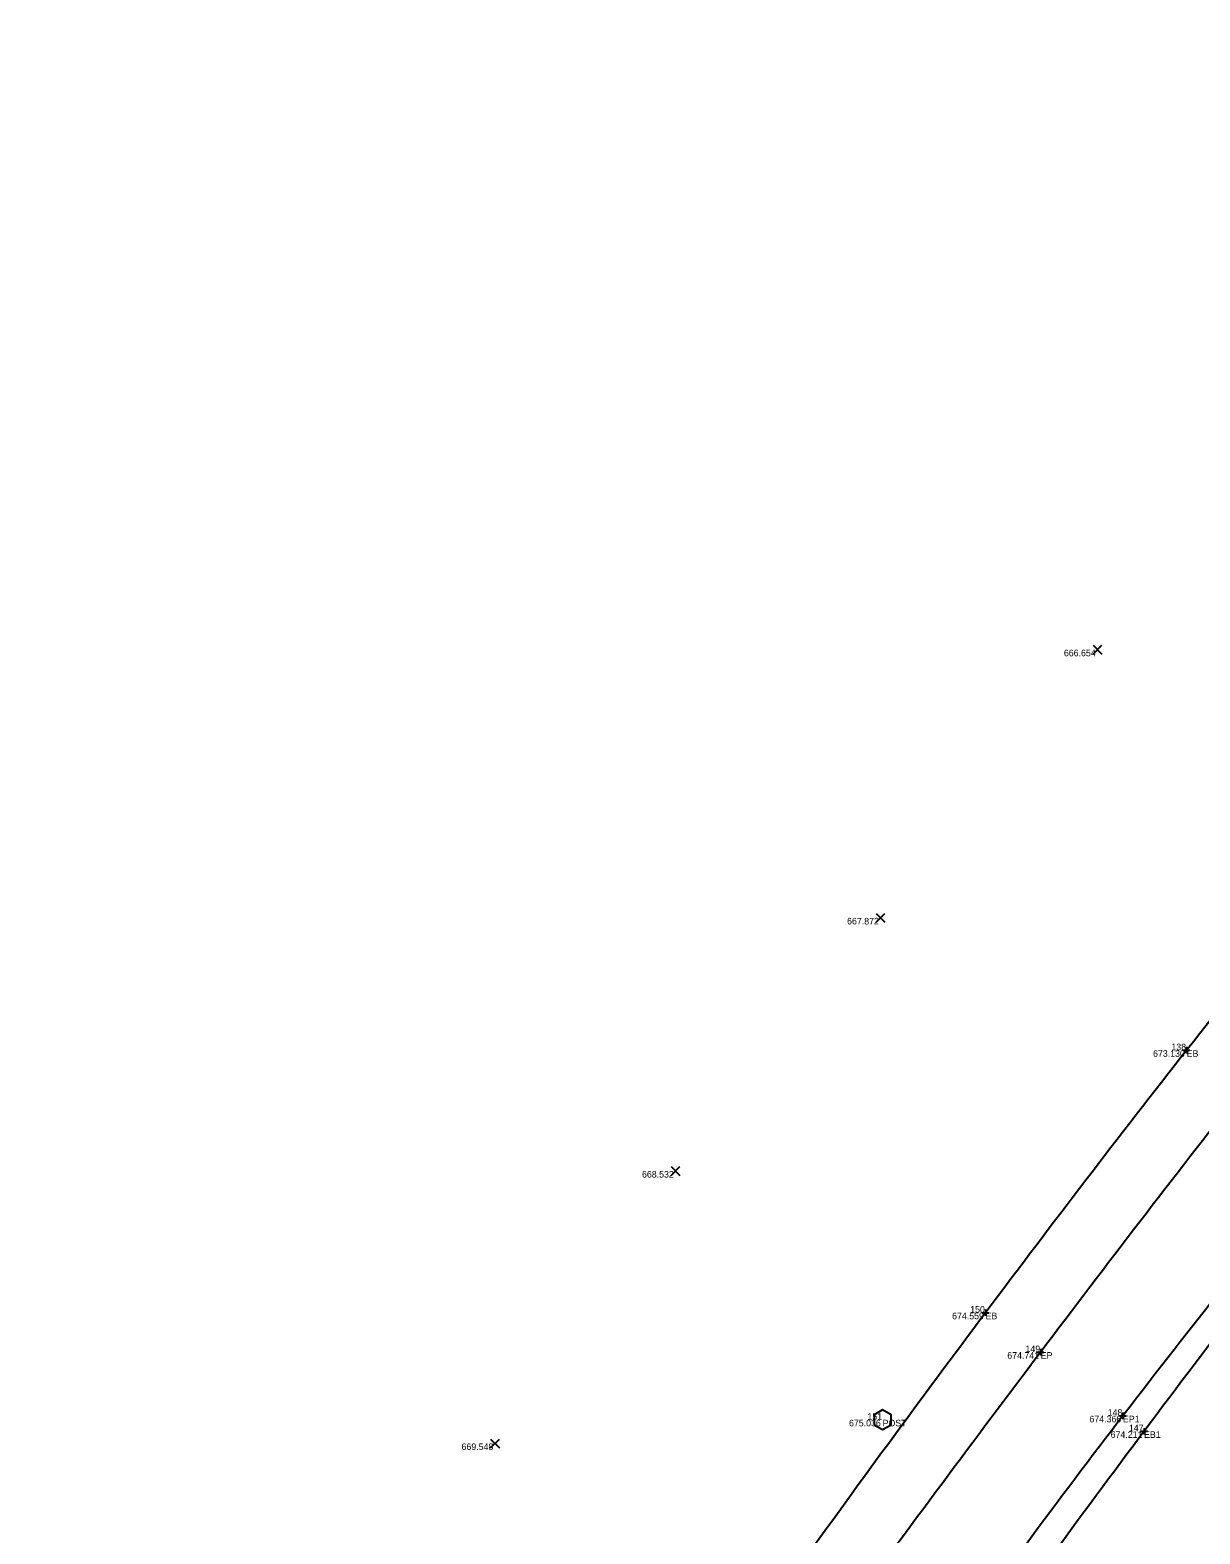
# Model space of a CAD drawing. Extents: x 2197382 to 2204062, y 634117 to 636522.
# Drawn here: x 2202128.8 to 2202306.8, y 634830.5 to 635059.1 of the extents above; entities that cross this region are included whole.
import ezdxf

# ---------------------------------------------------------------- set-up
doc = ezdxf.new("R2010")
doc.units = 0
for name, color, linetype in [('_CIVIL_CONSTRUCTION', 7, 'Continuous'), ('GE_P_Alignment_100_Distances', 7, 'Continuous'), ('GE_X_Alignment', 7, 'Continuous'), ('RW_X_CL_100_Cardinal_Points', 7, 'Continuous'), ('RW_X_CL_100_Curve_Data', 7, 'Continuous'), ('SH_Border', 7, 'Continuous'), ('SH_Cut_Line', 7, 'Continuous'), ('SH_Data', 7, 'Continuous')]:
    doc.layers.add(name, color=color, linetype=linetype)

msp = doc.modelspace()

# ---------------------------------------------------------------- linework, layer by layer
at = {"layer": '_CIVIL_CONSTRUCTION'}
for p, q in [((2202304.24, 634904.01), (2202305.24, 634904.01)), ((2202304.74, 634904.51), (2202304.74, 634903.51)), ((2202304.74, 634904.01), (2202304.74, 634904.01)), ((2202273.66, 634864.12), (2202274.66, 634864.12)), ((2202274.16, 634864.62), (2202274.16, 634863.62)), ((2202274.16, 634864.12), (2202274.16, 634864.12)), ((2202282.04, 634858.12), (2202283.04, 634858.12)), ((2202282.54, 634858.62), (2202282.54, 634857.62)), ((2202282.54, 634858.12), (2202282.54, 634858.12)), ((2202294.55, 634848.45), (2202295.55, 634848.45)), ((2202295.05, 634848.95), (2202295.05, 634847.95)), ((2202295.05, 634848.45), (2202295.05, 634848.45)), ((2202297.76, 634846.09), (2202298.76, 634846.09)), ((2202298.26, 634846.59), (2202298.26, 634845.59)), ((2202298.26, 634846.09), (2202298.26, 634846.09))]:
    msp.add_line(p, q, dxfattribs=at)
at = {"layer": 'GE_P_Alignment_100_Distances'}
for points in [[(2202514.19, 635120), (2202501.95, 635108.79), (2202477.63, 635085.87), (2202443.41, 635049.36), (2202409.55, 635012.34), (2202376.26, 634974.99), (2202344.34, 634936.42), (2202312.72, 634897.79), (2202282.43, 634858.12), (2202252.58, 634818.18), (2202223.74, 634777.45), (2202196.69, 634735.5), (2202169.8, 634693.41), (2202144.64, 634650.36), (2202119.18, 634607.44), (2202097.03, 634562.79), (2202074.71, 634518.18), (2202053.15, 634473.28), (2202032.85, 634427.72), (2202013.67, 634381.72), (2201995.41, 634335.21), (2201979.19, 634288.02), (2201963.55, 634240.68), (2201953.92, 634208.98), (2201949.13, 634193.1)], [(2202525.02, 635108.11), (2202513.04, 635097.11), (2202489.33, 635074.07), (2202455.07, 635038.62), (2202421.29, 635002.1), (2202388.81, 634964.35), (2202356.35, 634926.75), (2202325.87, 634887.43), (2202295, 634848.95), (2202265.53, 634808.92), (2202237.35, 634768.89), (2202211.52, 634726.54), (2202183.6, 634685.47), (2202158.14, 634642.34), (2202133.69, 634599.43), (2202111.05, 634555.42), (2202088.76, 634511.33), (2202068.04, 634466.33), (2202047.21, 634421.56), (2202027.88, 634376.06), (2202010.16, 634329.7), (2201994.09, 634282.81), (2201978.74, 634235.43), (2201968.75, 634203.87), (2201963.85, 634187.95)]]:
    msp.add_open_spline(points, degree=3, dxfattribs=at)
at = {"layer": 'GE_X_Alignment'}
for points in [[(2202540.06, 635152.93), (2202529.43, 635144.25), (2202507.23, 635123.46), (2202471.72, 635092.05), (2202435.62, 635056.76), (2202402.1, 635018.87), (2202368.73, 634981.48), (2202336.15, 634943.25), (2202304.62, 634904.21), (2202274.11, 634864.33), (2202244.37, 634823.83), (2202215.65, 634782.83), (2202187.65, 634741.05), (2202161.54, 634698.56), (2202134.84, 634656), (2202111.41, 634611.66), (2202087.71, 634567.52), (2202064.97, 634523.35), (2202044.2, 634477.97), (2202023.42, 634432.25), (2202003.66, 634386.18), (2201990.91, 634355.55), (2201984.79, 634340.33)], [(2202570.92, 635145.14), (2202556.1, 635132.41), (2202530.6, 635107.02), (2202492.19, 635071.28), (2202457.98, 635035.82), (2202424.73, 634999.38), (2202391.64, 634962.22), (2202359.56, 634924.46), (2202328.32, 634885.6), (2202298.37, 634846.53), (2202268.85, 634806.21), (2202240.94, 634765.59), (2202212.91, 634724.71), (2202187.2, 634682.69), (2202161.14, 634640.35), (2202137.99, 634596.95), (2202114.64, 634553.56), (2202092.28, 634509.95), (2202071.73, 634464.7), (2202050.81, 634420.11), (2202031.84, 634374.34), (2202014.23, 634328.21), (2201997.98, 634281.03), (2201983.22, 634233.69), (2201972.74, 634202.38), (2201968.03, 634186.79)]]:
    msp.add_open_spline(points, degree=3, dxfattribs=at)
at = {"layer": 'RW_X_CL_100_Cardinal_Points'}
msp.add_lwpolyline([(2202257.2, 634847.09), (2202258.5, 634846.34), (2202259.79, 634847.09), (2202259.79, 634848.59), (2202258.5, 634849.34), (2202257.2, 634848.59), (2202257.2, 634847.09)], dxfattribs=at)
at = {"layer": 'RW_X_CL_100_Curve_Data'}
for p, q in [((2202290.52, 634964.23), (2202291.86, 634965.56)), ((2202290.52, 634965.56), (2202291.86, 634964.23)), ((2202257.51, 634923.46), (2202258.84, 634924.8)), ((2202257.51, 634924.8), (2202258.84, 634923.46)), ((2202226.32, 634884.98), (2202227.65, 634886.32)), ((2202226.32, 634886.32), (2202227.65, 634884.98)), ((2202198.89, 634843.58), (2202200.23, 634844.91)), ((2202198.89, 634844.91), (2202200.23, 634843.58))]:
    msp.add_line(p, q, dxfattribs=at)

# ---------------------------------------------------------------- texts
at = {"layer": 'SH_Border'}
for s, p in [('EB', (2202304.74, 634903.01)), ('EB', (2202274.16, 634863.12)), ('EP', (2202282.54, 634857.12)), ('POST', (2202258.5, 634846.84)), ('EP1', (2202295.05, 634847.45)), ('EB1', (2202298.26, 634845.09))]:
    msp.add_text(s, height=1, dxfattribs=at).set_placement(p)
at = {"layer": 'SH_Cut_Line'}
for s, p in [('138', (2202302.42, 634904.01)), ('150', (2202271.82, 634864.12)), ('149', (2202280.23, 634858.12)), ('151', (2202256.19, 634847.84)), ('148', (2202292.73, 634848.45)), ('147', (2202295.95, 634846.09))]:
    msp.add_text(s, height=1, dxfattribs=at).set_placement(p)
at = {"layer": 'SH_Data'}
for s, p in [('666.654', (2202286.07, 634963.89)), ('667.872', (2202253.1, 634923.13)), ('673.130', (2202299.63, 634903.01)), ('668.532', (2202221.91, 634884.65)), ('674.559', (2202269.07, 634863.12)), ('674.741', (2202277.46, 634857.12)), ('675.036', (2202253.39, 634846.84)), ('674.366', (2202289.95, 634847.45)), ('674.211', (2202293.18, 634845.09)), ('669.548', (2202194.46, 634843.24))]:
    msp.add_text(s, height=1, dxfattribs=at).set_placement(p)

doc.saveas('drawing.dxf')
